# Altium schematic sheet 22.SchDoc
size 299 x 210 mm
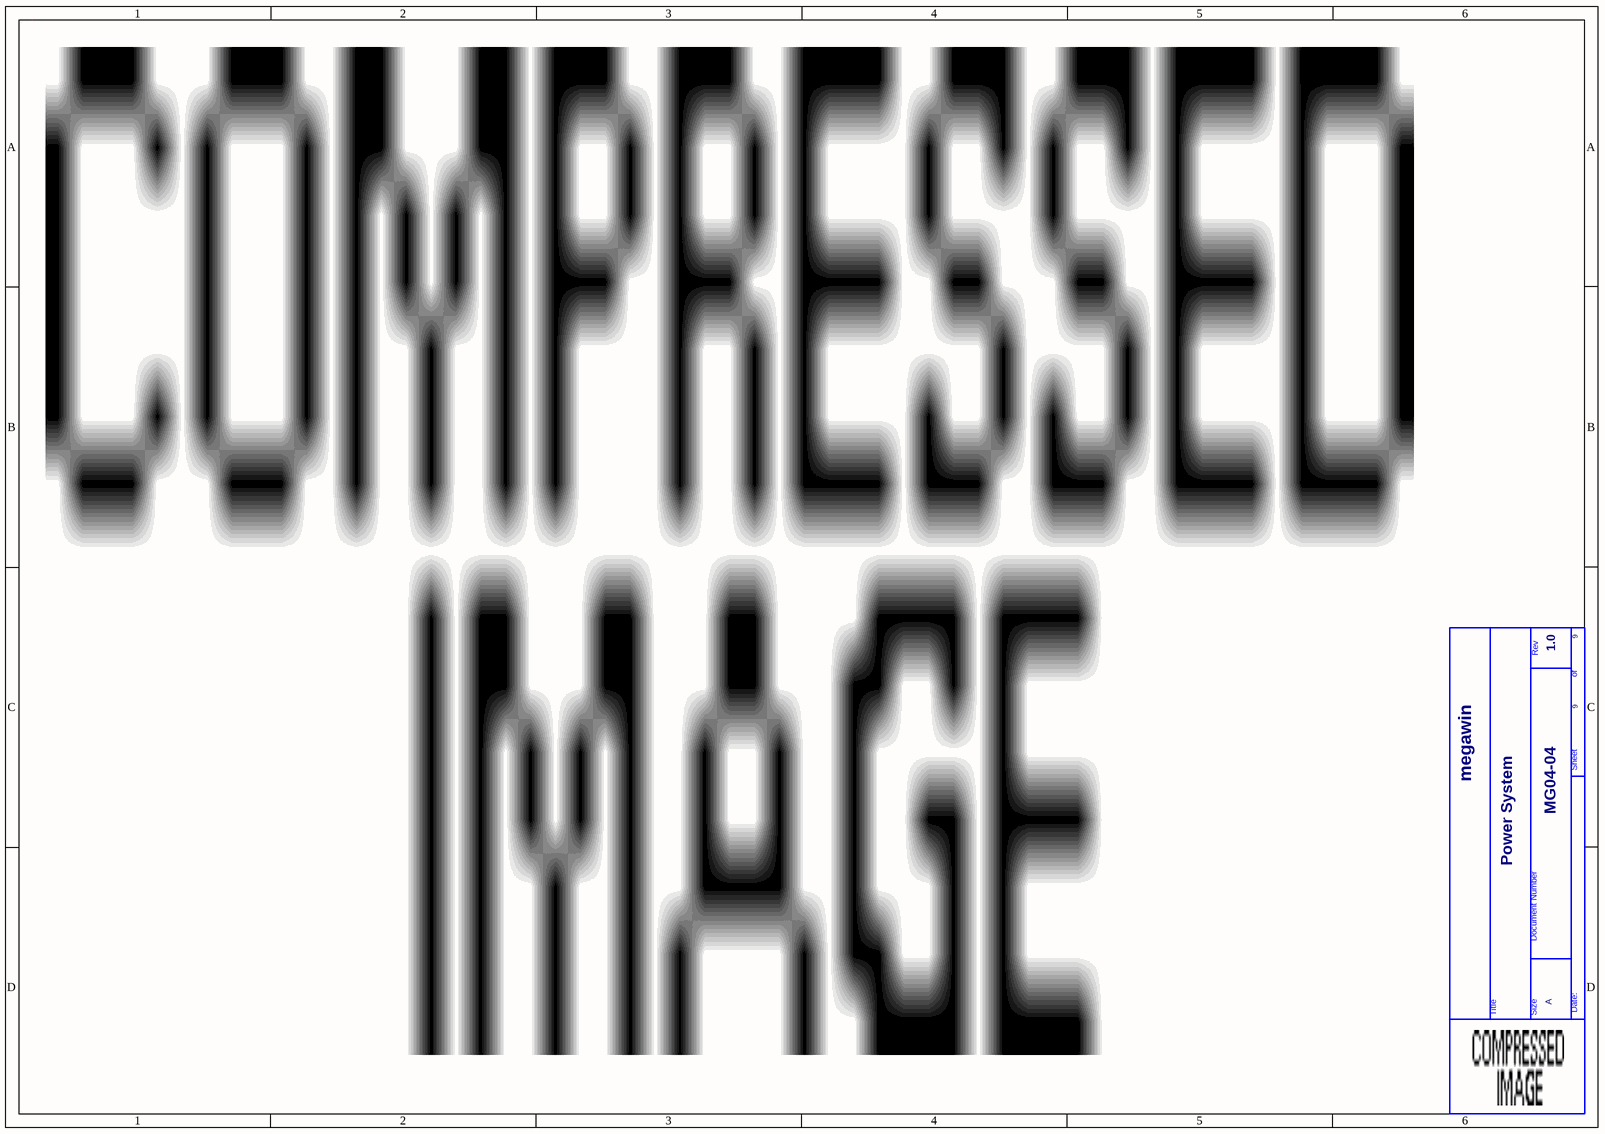
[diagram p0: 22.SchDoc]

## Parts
*  OrgName: megawin  Doc: MG04-04  RevCode: 1.0  Title: Power System  Page Size: A  Page Number: 9  (hidden comment: TitleBlock_MegaWin_V)  (graphical)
